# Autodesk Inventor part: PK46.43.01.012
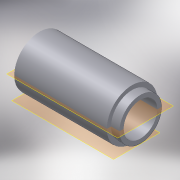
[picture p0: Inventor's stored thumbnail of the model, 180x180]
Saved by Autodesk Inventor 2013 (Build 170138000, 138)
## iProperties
Created: 2005-04
Part Number: PK46.43.01.012
Document SubType Name: Modeling
Designer: elarisa
Manufacturer: Standard
Standards Organization: Custom
Material: Steel, Mild
Density: 7.86 g/cm^3
Author: elarisa
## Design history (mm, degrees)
sketch "Эскиз1"
  geometry: L1 (-16.532, 5.23)-(-16.532, 20.23); L2 (-16.532, 20.23)-(38.468, 20.23); L3 (43.468, 17.73)-(43.468, 5.23); L4 (-16.532, 5.23)-(43.468, 5.23); L5 (43.468, 15.23)-(-6.532, 15.23); L6 (-6.532, 15.23)-(-12.305, 5.23); L7 (43.468, 17.73)-(38.468, 17.73); L8 (38.468, 17.73)-(38.468, 20.23)
  constraints: 16 end point, 3 parallel, 3 perpendicular, 2 point on line, 1 vertical
  dimensions: "d7" = 30 diameter of L2 L4; "d8" = 20 diameter of L5 L4; "d9" = 120 deg angle of L5 L6; "d11" = 50 distance of L5.start L5.end; "d22" = 5 distance of L3.start L7.end; "d23" = 25 diameter of L7 L4; "d24" = 60 distance between parallel lines of L1 L3
revolve "Вращение1" sketch "Эскиз1" stored, may be unused: angle "d12" = 90 deg
node "РабПлоскость1"
sketch "Эскиз2"
  geometry: L1 (-27.5, -15)-(27.5, -15) reference; L2 (-27.5, 15)-(27.5, 15) reference; L3 (27.5, -15)-(27.5, 15) reference; L4 (32.5, -12.5)-(32.5, 12.5) reference; L5 (-27.5, -15)-(-27.5, 15) reference; 1 further point
  dimensions: "d13" = 15 distance from line of L1 point (-7.5, 0); "d27" = 20 distance from line of point (-7.5, 0) L5
hole "Отверстие1" sketch "Эскиз2" diameter "d15" = 20; stored, may be unused: countersink angle "d19" = 90 deg, drill point angle "d21" = 118 deg; dims "d16" = 6, "d17" = 26, "d18" = 3, "d20" = 15
body "Solid1"
